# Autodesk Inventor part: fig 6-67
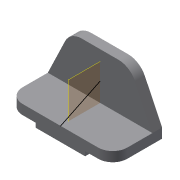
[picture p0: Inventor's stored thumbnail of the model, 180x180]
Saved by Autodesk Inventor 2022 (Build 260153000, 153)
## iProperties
Created: 2001-12
Part Number: fig 6-67
Document SubType Name: Modeling
Designer: Renu Muthoo
Density: 1 g/cm^3
Material: Generic
Appearance: Default
Control State: 0
Master: False
Checked Out: False
Shininess: 77.0
Length Units: 11269
Angle Units: 11279
Time Units: 11290
Mass Units: 11283
Length Display Precision: 3
Angle Display Precision: 2
Density: 0.0
Volumn: 0.0
Area: 0.0
PropertySet Name: Model Information
Author: Renu Muthoo
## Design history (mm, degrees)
node "Sketch1"
sketch "Sketch2"
  geometry: L1 (-67.219, 19.116)-(148.781, 19.116); L2 (148.781, 19.116)-(148.781, -0.884); L3 (-67.219, -0.884)-(-67.219, 19.116); L4 (-10.219, -0.884)-(-10.219, -9.884); L5 (-10.219, -9.884)-(91.781, -9.884); L6 (91.781, -9.884)-(91.781, -0.884); L7 (148.781, -0.884)-(91.781, -0.884); L8 (-10.219, -0.884)-(-67.219, -0.884)
  constraints: 16 end point, 5 parallel, 4 perpendicular, 2 equal length, 1 horizontal
  dimensions: "d0" = 102 distance of L4.end L5.end; "d1" = 57 distance of L4.start L3.start; "d2" = 29 distance between parallel lines of L1 L5; "d3" = 20 distance of L1.end L2.end
extrude "Extrusion1" new body sketch "Sketch2" distance "d4" = 102; taper "d5" = 0 deg
sketch "Sketch3"
  geometry: L1 (67.219, -19.116)-(-148.781, -19.116) reference; L2 (67.219, -19.116)-(31.475, -93.564); L3 (-2.781, -115.116)-(-78.781, -115.116); L4 (-113.038, -93.564)-(-148.781, -19.116); A1 r 38 centre (-2.781, -77.116) between (-2.781, -115.116) and (31.475, -93.564); A2 r 38 centre (-78.781, -77.116) between (-113.038, -93.564) and (-78.781, -115.116)
  constraints: 6 end point, 4 point on circle, 4 tangent, 2 centre point, 1 equal length, 1 equal radius, 1 parallel
  dimensions: "d6" = 96 distance between parallel lines of L3 L1; "d7" = 38 radius of A1; "d8" = 76 distance of A2.centre A1.centre
extrude "Extrusion2" join sketch "Sketch3" distance "d9" = 20; taper "d10" = 0 deg
fillet "Fillet1" dims "d11" = 30
workplane "Work Plane1"
sketch "Sketch7"
  geometry: L1 (0, -82)-(-39.557, 0)
  constraints: 2 end point
body "Solid1"
other parameters: "d12" = -108
